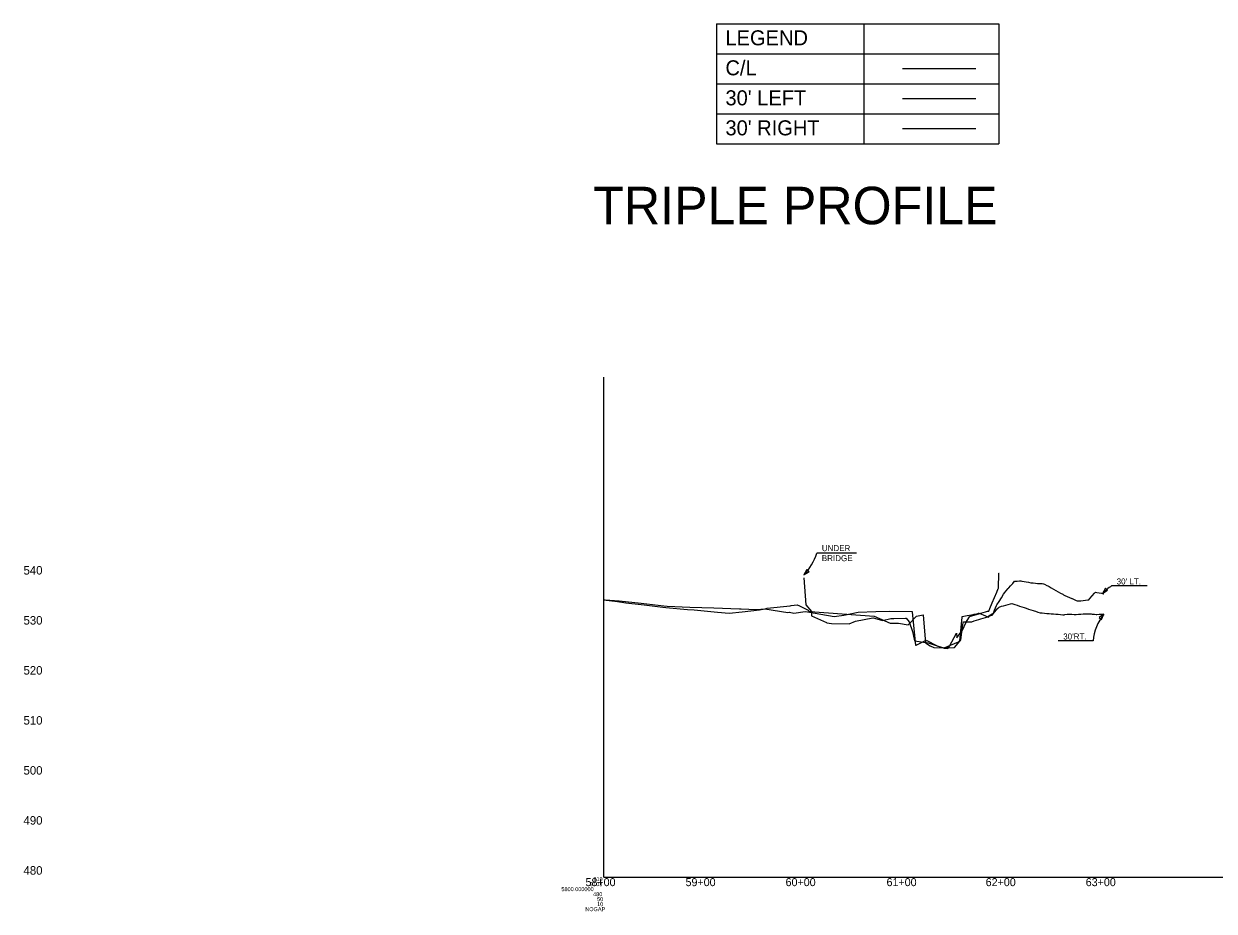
# Model space of a CAD drawing. Extents: x -767 to 1613, y -528 to 534.
# Drawn here: x -767 to 423, y -528 to 359 of the extents above; entities that cross this region are included whole.
import ezdxf

# ---------------------------------------------------------------- set-up
doc = ezdxf.new("R2010")
doc.units = 0
for name, color, linetype in [('Level 40', 7, 'Continuous'), ('Level 41', 7, 'Continuous'), ('Level 42', 7, 'Continuous'), ('Level 45', 7, 'Continuous'), ('Level 63', 7, 'Continuous')]:
    doc.layers.add(name, color=color, linetype=linetype)

msp = doc.modelspace()

# ---------------------------------------------------------------- linework, layer by layer
at = {"layer": 'Level 40'}
msp.add_line((111.5, 254.5), (184.5, 254.5), dxfattribs=at)
for points in [[(12.8, -194.7), (14.8, -221.6), (20.3, -228.4), (20.5, -232.7), (35.3, -239.4), (35.8, -239.7), (40.4, -240.4), (58.2, -240.6), (64.5, -237.9), (81.6, -234.5), (82, -234.5), (82, -234.5), (91.3, -237.3), (99.8, -235.2), (102.7, -235.2), (114.3, -235.1), (114.7, -234.9), (114.9, -234.9), (118.1, -238.6), (121.2, -248.3), (123.4, -257.7), (134.6, -259.2), (135.4, -259.3), (137, -259.8), (153.1, -264.9), (156.8, -265.2), (158.3, -263), (165.3, -249.9), (165.8, -254.5), (170.1, -248.7), (171, -247.6), (175, -239.1), (176.1, -237.3), (178.4, -233.7), (178.7, -233.3), (179.4, -233), (180.7, -232.7), (182.9, -232), (185.2, -231.3), (187.5, -230.6), (189.7, -229.9), (192, -229.2), (194.3, -228.5), (196.3, -227.9), (196.6, -228.1), (196.6, -228.1), (197.6, -228), (198.8, -225.2), (201.1, -219.8), (203.4, -214.4), (205.6, -209), (207.1, -205.4), (207.2, -205.1), (207.8, -189.9), (207.9, -190.1)], [(-187.3, -216.7), (-184.7, -217), (-173.5, -218.4), (-165.3, -219.7), (-147, -221.8), (-128.3, -223.9), (-125.2, -224.2), (-103.7, -226.2), (-96.9, -226.5), (-73.6, -228.9), (-61.8, -230.1), (-48.9, -228.6), (-31.6, -226.5), (-26.3, -225.8), (-3.2, -229.2), (-2, -229), (-1.7, -228.9), (2.6, -230), (14, -228.4), (16.4, -228.5), (43.1, -233.3), (52.8, -232.1), (67.1, -229.1), (84.6, -228.2), (97.9, -228), (121, -228.3), (121.1, -228.3), (121.1, -228.9), (124.3, -262.1), (124.9, -261.9), (135.1, -257), (146.8, -263), (152.9, -264.7), (167.3, -258.6), (169.6, -256.8), (171.8, -241.3), (172.2, -238.5), (176.1, -238.7), (178.4, -238.8), (179.8, -238.8), (180.7, -238.6), (182.9, -237.8), (185.2, -237.1), (187.5, -236.4), (189.7, -235.6), (192, -234.9), (194.3, -234.2), (196.6, -233.5), (198.8, -232.8), (201, -232.1), (201.1, -232), (203.4, -229.1), (205.6, -226.2), (206.5, -225.1), (207.1, -224.9), (207.7, -224.2), (207.9, -224.1), (210.2, -223), (210.3, -223), (212.4, -222.5), (214.7, -222.1), (214.7, -222.1), (217, -221.4), (219.3, -220.7), (220.5, -220.3), (221.5, -220.6), (223.8, -221.4), (226.1, -222.1), (228.3, -222.9), (230.6, -223.6), (232.9, -224.3), (235.1, -225.1), (237.4, -225.9), (239.7, -226.6), (242, -227.4), (243, -227.7), (244.2, -228.1), (246.5, -228.9), (248.8, -229.7), (248.8, -229.7), (251, -229.8), (253.3, -230), (255.6, -230.2), (257.9, -230.4), (260.1, -230.5), (262.4, -230.7), (264.7, -230.9), (266.9, -231.1), (269.2, -231.3), (271.5, -231.5), (272.8, -231.6), (273.7, -231.4), (276, -230.9), (276.2, -230.9), (278.3, -231), (280.6, -231.1), (282.8, -231.2), (284.8, -231.3), (285.1, -231.3), (287.4, -231.1), (289.6, -230.9)], [(289.6, -230.9), (291.9, -230.7), (294.2, -230.6), (295.5, -230.5), (296.5, -230.5), (298.7, -230.7), (300, -230.8), (301, -230.9), (303.3, -231.1), (304.8, -231.2), (305.5, -231.2), (307.8, -231.1), (310.1, -231), (312.3, -230.9), (312.7, -230.9)]]:
    msp.add_lwpolyline(points, dxfattribs=at)
at = {"layer": 'Level 41'}
for p, q in [((-74.7, 359.2), (207.6, 359.2)), ((-74.7, 359.2), (-74.7, 239.2)), ((72.6, 359.2), (72.6, 239.2)), ((207.6, 359.2), (207.6, 239.2)), ((-74.7, 329.2), (207.6, 329.2)), ((-74.7, 299.2), (207.6, 299.2)), ((-74.7, 269.2), (207.6, 269.2)), ((-74.7, 239.2), (207.6, 239.2)), ((65.3, -170), (25.7, -170)), ((356, -202.8), (320.4, -202.8)), ((301.8, -257.8), (267, -257.8))]:
    msp.add_line(p, q, dxfattribs=at)
for points in [[(15.7, -186.5), (12.8, -191.7), (18, -188.6)], [(314.1, -204.9), (311.2, -210.2), (316.3, -207)], [(310.2, -236.4), (312.7, -230.9), (307.8, -234.4)]]:
    msp.add_lwpolyline(points, close=True, dxfattribs=at)
for centre, radius, start, end in [((-26.8, -153.7), 54.9, 316.1656, 342.7511), ((343, -240.1), 43.6, 121.1891, 136.7876), ((351, -262.1), 49.4, 140.7968, 174.9645)]:
    msp.add_arc(centre, radius, start, end, dxfattribs=at)
at = {"layer": 'Level 45'}
for p, q in [((111.5, 314.5), (184.5, 314.5)), ((111.5, 284.5), (184.5, 284.5))]:
    msp.add_line(p, q, dxfattribs=at)
for points in [[(-187.3, -216.4), (-185.9, -216.5), (-171.8, -217.5), (-149.7, -220), (-127.3, -222.6), (-124, -223), (-101.2, -223.9), (-77.2, -224.8), (-51.7, -225.8), (-49.9, -225.8), (-34.6, -226.4), (-26, -225.5), (-24, -225), (-0.9, -222.5), (0.1, -222.2), (6.2, -221.5), (8.4, -222.8), (17.1, -226.9), (17.3, -227.3), (17.5, -228.1), (18.1, -228.2), (19.1, -228.2), (83, -233), (99.1, -239.9), (107.3, -240), (117, -241.6), (125.3, -232.9), (131.9, -231.6), (132.7, -239.9), (134.5, -259.8), (139, -262.6), (142.6, -264.3), (156, -264.6), (163.2, -264.2), (167, -260.1), (168.8, -257.9), (171.1, -234.1), (171.1, -233.2), (172.7, -232.9), (176.1, -232.3), (178.4, -231.9), (180.7, -231.5), (182.9, -231.1), (185.2, -230.6), (185.9, -230.5), (187.4, -229.9), (187.5, -229.9), (189.7, -230.7), (190.4, -230.9), (192, -231.6), (194.3, -232.6), (196.6, -233.6), (197.5, -234), (198.1, -232.4), (198.8, -232), (201.1, -230.6), (202.2, -230), (203.4, -227.1), (205.4, -222.2), (205.6, -221.8), (207.9, -218.3), (210.2, -214.7), (212.4, -211.1), (213.6, -209.3), (214.7, -208), (217, -205.3), (217.5, -204.7), (219.3, -202.7), (221.5, -200.2), (223.3, -198.1), (223.8, -198), (224.3, -197.9), (226.1, -197.9), (228.3, -197.8), (229.7, -197.7), (230.6, -197.9), (232.9, -198.3), (235.1, -198.7), (237.4, -199.1), (239.7, -199.5), (242, -199.8), (244.2, -200.1), (246.3, -200.3), (246.5, -200.3), (248.8, -200.2), (248.8, -200.2), (251, -200.4), (252.2, -200.5), (253.3, -201), (255.6, -202.2), (256.5, -202.6), (257.9, -203.4), (260.1, -204.7), (262.4, -206.1), (264.7, -207.3), (266.9, -208.6), (269.2, -209.9), (271.5, -211.1), (272.4, -211.6), (273.7, -212.2), (276, -213.2)], [(276, -213.2), (278.3, -214.2), (280.6, -215.2), (281, -215.4), (282.8, -216.3), (285.1, -217.4), (286.1, -217.8), (287.4, -217.7), (289.6, -217.5), (291.9, -217.2), (294.2, -217), (296.5, -216.7), (297.4, -216.6), (297.6, -216.6), (298.7, -215.3), (301, -212.7), (303.3, -210), (304.2, -209), (305.5, -209.2), (307.8, -209.6), (310.1, -210), (311.2, -210.2), (312.3, -210.6), (312.7, -210.7)]]:
    msp.add_lwpolyline(points, dxfattribs=at)
at = {"layer": 'Level 63'}
for q in [(-187.3, 6.1), (1612.7, -493.9), (-187.3, -493.9)]:
    msp.add_line((-187.3, -493.9), q, dxfattribs=at)

# ---------------------------------------------------------------- texts
at = {"layer": 'Level 41'}
for s, height, p in [('LEGEND', 15, (-65.6, 337.7)), ('C/L ', 15, (-65.6, 307.7)), ("30' LEFT", 15, (-65.6, 277.7)), ("30' RIGHT", 15, (-65.6, 247.7)), ('TRIPLE PROFILE', 37.5, (-197.7, 158.8)), ('UNDER', 6, (30.7, -168)), ('BRIDGE', 6, (30.7, -178)), ("30' LT.", 6, (325.4, -201.3)), ("30'RT.", 6, (272, -256.3))]:
    msp.add_text(s, height=height, dxfattribs=at).set_placement(p)
at = {"layer": 'Level 42'}
for s, height, p in [('540', 8.5, (-767.2, -191.4)), ('530', 8.5, (-767.2, -241.4)), ('520', 8.5, (-767.2, -291.4)), ('510', 8.5, (-767.2, -341.4)), ('500', 8.5, (-767.2, -391.4)), ('490', 8.5, (-767.2, -441.4)), ('480', 8.5, (-767.2, -491.4)), ('58+00', 8, (-205.5, -502.9)), ('59+00', 8, (-105.5, -502.9)), ('60+00', 8, (-5.5, -502.9)), ('61+00', 8, (95.4, -502.9)), ('62+00', 8, (194.5, -502.9)), ('63+00', 8, (294.5, -502.9))]:
    msp.add_text(s, height=height, dxfattribs=at).set_placement(p)
at = {"layer": 'Level 63'}
for s, p in [('S103', (-201.5, -502.9)), ('919', (-197.6, -497.9)), ('5800.000000', (-229.6, -507.9)), ('480', (-197.9, -512.9)), ('50', (-193.9, -517.9)), ('10', (-193.9, -522.9)), ('NOGAP', (-205.7, -527.9))]:
    msp.add_text(s, height=4, dxfattribs=at).set_placement(p)

doc.saveas('drawing.dxf')
